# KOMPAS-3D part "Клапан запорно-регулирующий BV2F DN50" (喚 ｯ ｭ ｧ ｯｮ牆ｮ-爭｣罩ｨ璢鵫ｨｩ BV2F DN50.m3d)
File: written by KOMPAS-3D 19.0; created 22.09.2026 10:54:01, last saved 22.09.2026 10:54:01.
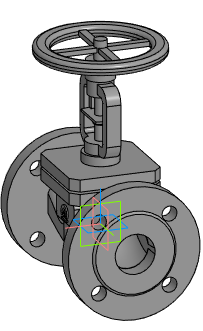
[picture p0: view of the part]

Document properties: Автор: Энергия; Полное имя файла: Z:\3.Личные\sachek\Dendor\_3D для проектировщиков\5.7 Клапан запорно-регулирующий BV2F\BV2F_STP\Клапан запорно-регулирующий BV2F DN50.m3d

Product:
- Part/product: Клапан запорно-регулирующий BV2F DN50

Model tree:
1. Операция без истории:1  (labels: Клапан запорно-регулирующий BV2F DN50)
